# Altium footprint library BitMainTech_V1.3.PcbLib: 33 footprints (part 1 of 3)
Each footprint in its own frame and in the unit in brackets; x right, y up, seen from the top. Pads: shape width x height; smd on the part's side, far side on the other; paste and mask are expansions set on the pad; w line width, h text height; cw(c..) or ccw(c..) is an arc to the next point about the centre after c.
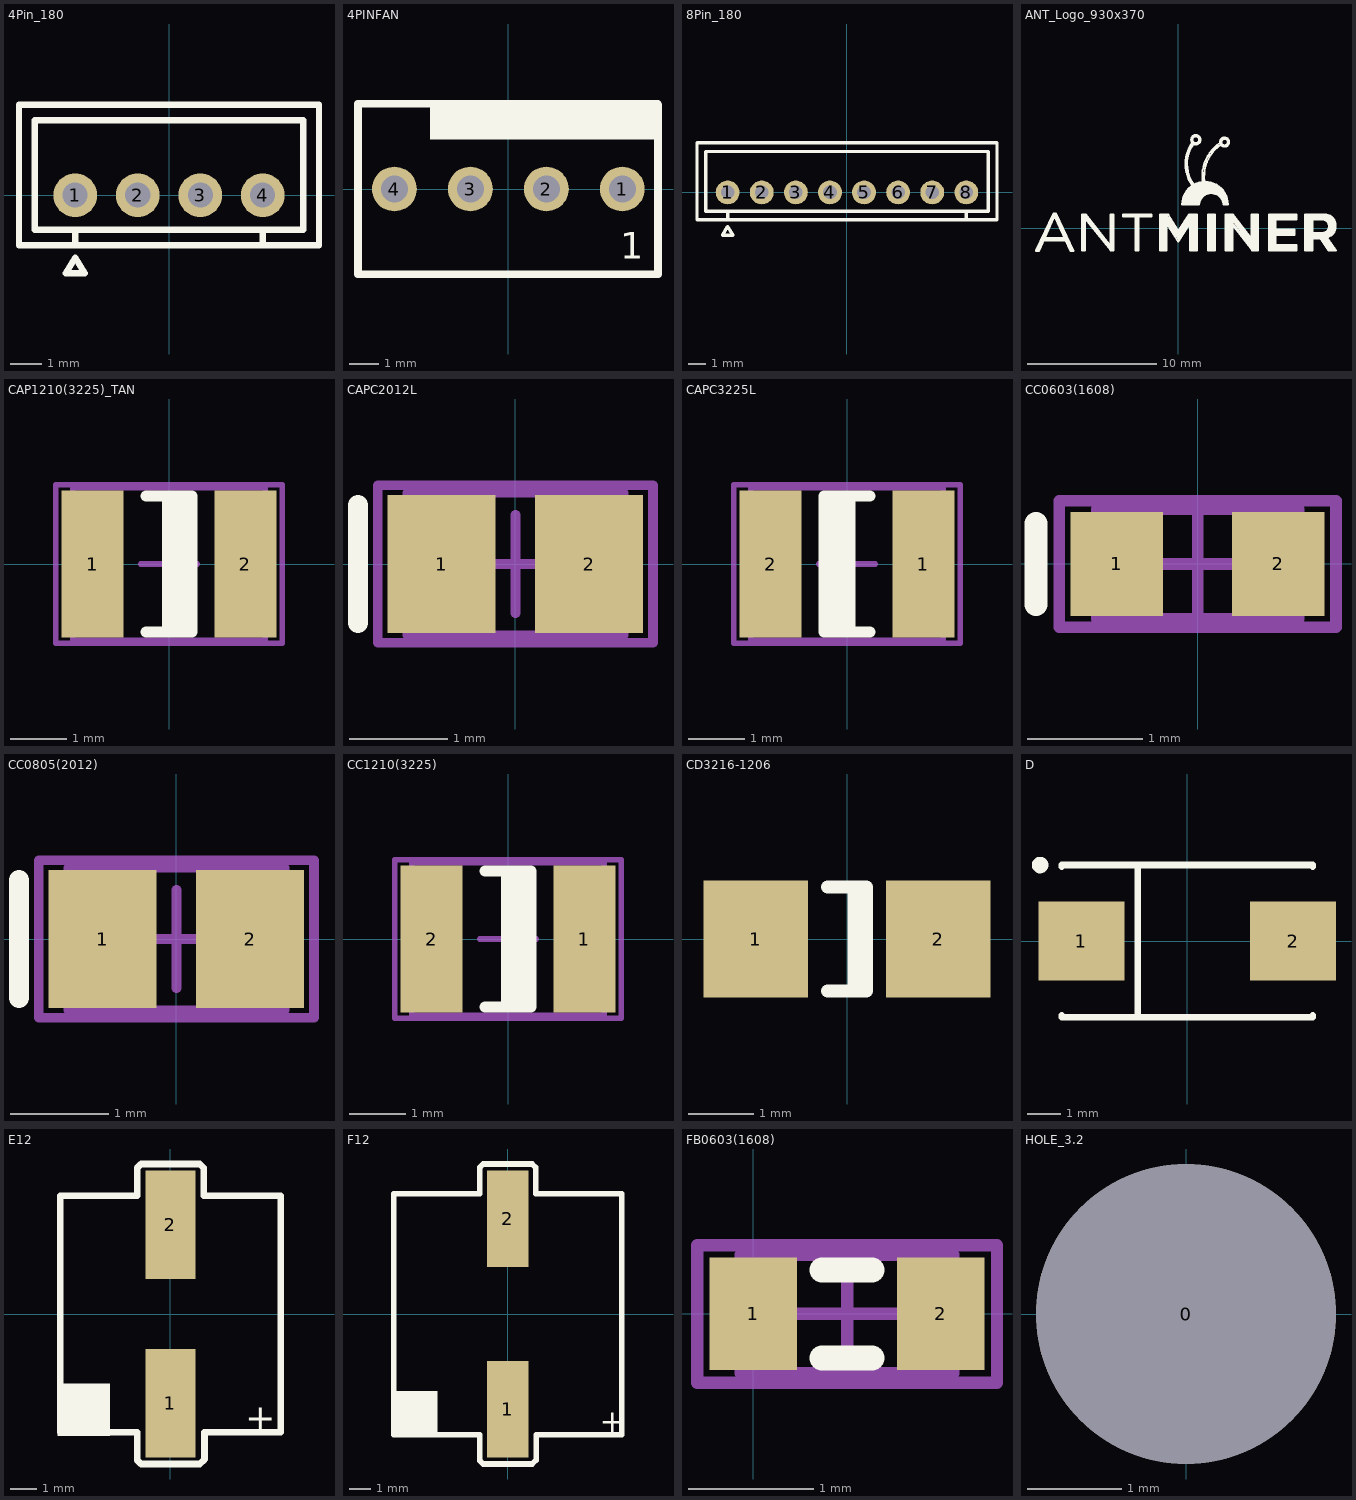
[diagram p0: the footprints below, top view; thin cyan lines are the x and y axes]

## 4Pin_180 [mm]
height 6.8
pads (4):
  round 1.4 hole 0.8: 1(-3,0) 2(-1,0) 3(1,0) 4(3,0)
Top Overlay:
  lines w0.203: -3,-1.6 -3,-1.1 ; 3,-1.6 3,-1.1 ; -4.8,-1.6 4.8,-1.6 4.8,2.9 -4.8,2.9 -4.8,-1.6 ; -4.3,-1.1 4.3,-1.1 4.3,2.4 -4.3,2.4 -4.3,-1.1 ; -3.3,-2.5 -3,-2 -2.7,-2.5 -3.3,-2.5

## 4PINFAN [mm]
height 18.15
pads (4):
  round 1.5 hole 0.9 paste+0.05 mask+0.05: 1(3.81,0) 2(1.27,0) 3(-1.27,0) 4(-3.81,0)
Top Overlay:
  rectangle: -2.617,1.651 4.927,2.794
  lines w0.254: 5,2.85 -5.029,2.85 -5.029,-2.845 -5.024,-2.85 5.004,-2.85 5.004,2.819
  text "1" at 3.734,-2.337 h0.89

## 8Pin_180 [mm]
height 6.8
pads (8):
  round 1.4 hole 0.8: 1(-7,0) 2(-5,0) 3(-3,0) 4(-1,0) 5(1,0) 6(3,0) 7(5,0) 8(7,0)
Top Overlay:
  lines w0.203: -7,-1.6 -7,-1.1 ; 7,-1.6 7,-1.1 ; -8.8,-1.6 -8.8,2.9 8.8,2.9 8.8,-1.6 -8.8,-1.6 ; -8.3,-1.1 -8.3,2.4 8.3,2.4 8.3,-1.1 -8.3,-1.1 ; -7.3,-2.5 -6.7,-2.5 -7,-2 -7.3,-2.5

## ANT_Logo_930x370 [mm]
height 18.15
Top Overlay:
  drawing of 187 lines, arcs and shapes, not listed

## CAP1210(3225)_TAN [mm] "Chip Capacitor, Body 3.2x2.5mm, IPC High Density"
height 1.35
pads (2):
  rect 1.1x2.6 smd: 1(-1.35,0) 2(1.35,0)
Top Overlay:
  rectangle: -0.125,-1.2 0.425,1.2
  lines w0.2: -0.4,-1.2 0.4,-1.2 0.4,1.2 -0.4,1.2
Mechanical 13:
  lines w0.1: -1.7,-1.35 1.7,-1.35 1.7,1.35 -1.7,1.35 -1.7,-1.35
Mechanical 15:
  lines w0.1: -0.5,0 0.5,0 ; 0,-0.5 0,0.5 ; -2,-1.4 2,-1.4 2,1.4 -2,1.4 -2,-1.4
3D body: height 1.35, standoff 0, extent -1.7,-1.35 1.7,1.35

## CAPC2012L [mm] "Chip Capacitor, Body 2.0x1.3mm, IPC High Density"
height 1.1
pads (2):
  rect 1.1x1.4 smd: 1(-0.75,0) 2(0.75,0)
Top Overlay:
  lines w0.2: -1.6,-0.6 -1.6,0.6
Mechanical 13:
  lines w0.1: -1.1,-0.725 1.1,-0.725 1.1,0.725 -1.1,0.725 -1.1,-0.725
Mechanical 15:
  lines w0.1: -0.5,0 0.5,0 ; 0,-0.5 0,0.5 ; -1.4,-0.8 1.4,-0.8 1.4,0.8 -1.4,0.8 -1.4,-0.8
3D body: height 1.1, standoff 0, extent -1.1,-0.725 1.1,0.725

## CAPC3225L [mm] "Chip Capacitor, Body 3.2x2.5mm, IPC High Density"
height 1.35
pads (2):
  rect 1.1x2.6 smd: 1(1.35,0) 2(-1.35,0)
Top Overlay:
  rectangle: -0.4,-1.2 0.15,1.2
  lines w0.2: 0.4,-1.2 -0.4,-1.2 -0.4,1.2 0.4,1.2
Mechanical 13:
  lines w0.1: -1.7,-1.35 -1.7,1.35 1.7,1.35 1.7,-1.35 -1.7,-1.35
Mechanical 15:
  lines w0.1: -0.5,0 0.5,0 ; 0,-0.5 0,0.5 ; -2,-1.4 -2,1.4 2,1.4 2,-1.4 -2,-1.4
3D body: height 1.35, standoff 0, extent -1.7,-1.35 1.7,1.35

## CC0603(1608) [mm] "Chip Capacitor, Body 1.6x0.8mm, IPC High Density"
height 0.85
pads (2):
  rect 0.8x0.9 smd: 1(-0.7,0) 2(0.7,0)
Top Overlay:
  lines w0.2: -1.4,-0.35 -1.4,0.35
Mechanical 13:
  lines w0.1: -0.875,-0.475 0.875,-0.475 0.875,0.475 -0.875,0.475 -0.875,-0.475
Mechanical 15:
  lines w0.1: -0.475,0 0.475,0 ; 0,-0.475 0,0.475 ; -1.2,-0.55 1.2,-0.55 1.2,0.55 -1.2,0.55 -1.2,-0.55
3D body: height 0.85, standoff 0, extent -0.875,-0.475 0.875,0.475

## CC0805(2012) [mm] "Chip Capacitor, Body 2.0x1.3mm, IPC High Density"
height 1.1
pads (2):
  rect 1.1x1.4 smd: 1(-0.75,0) 2(0.75,0)
Top Overlay:
  lines w0.2: -1.6,-0.6 -1.6,0.6
Mechanical 13:
  lines w0.1: -1.1,-0.725 -1.1,0.725 1.1,0.725 1.1,-0.725 -1.1,-0.725
Mechanical 15:
  lines w0.1: -0.5,0 0.5,0 ; 0,-0.5 0,0.5 ; -1.4,-0.8 -1.4,0.8 1.4,0.8 1.4,-0.8 -1.4,-0.8
3D body: height 1.1, standoff 0, extent -1.1,-0.725 1.1,0.725

## CC1210(3225) [mm] "Chip Capacitor, Body 3.2x2.5mm, IPC High Density"
height 1.35
pads (2):
  rect 1.1x2.6 smd: 1(1.35,0) 2(-1.35,0)
Top Overlay:
  rectangle: -0.125,-1.2 0.425,1.2
  lines w0.2: -0.4,-1.2 0.4,-1.2 0.4,1.2 -0.4,1.2
Mechanical 13:
  lines w0.1: -1.7,-1.35 1.7,-1.35 1.7,1.35 -1.7,1.35 -1.7,-1.35
Mechanical 15:
  lines w0.1: -0.5,0 0.5,0 ; 0,-0.5 0,0.5 ; -2,-1.4 2,-1.4 2,1.4 -2,1.4 -2,-1.4
3D body: height 1.35, standoff 0, extent -1.7,-1.35 1.7,1.35

## CD3216-1206 [mm] "Chip Diode; Body 3.2 x 1.6 mm (LxW typ)"
height 1.35
pads (2):
  rect 1.6x1.8 smd: 1(-1.4,0) 2(1.4,0)
Top Overlay:
  lines w0.2: -0.3,-0.8 0.3,-0.8 0.3,0.8 -0.3,0.8 ; 0.11,-0.8 0.11,0.8

## D [mm] "Capacitor, SM Tantalum; Body 7.3 x 4.3 mm (LxW typ)"
height 3.1
pads (2):
  rect 2.6x2.4 smd: 1(-3.2,0) 2(3.2,0)
Top Overlay:
  circle w0.25: c-4.45,2.3 r0.125
  lines w0.2: -3.8,-2.25 -3.8,-2.3 3.8,-2.3 3.8,-2.25 ; -3.8,2.25 -3.8,2.3 3.8,2.3 3.8,2.25 ; -1.5,-2.3 -1.5,2.3

## E12 [mm] "SVP"
height 8.3
pads (2):
  rect 1.9x4.15 smd: 1(0,-3.4) 2(0,3.4)
Top Overlay:
  rectangle: -4.311,-4.641 -2.311,-2.641
  lines w0.254: -4.2,-4.5 -4.2,4.5 -2.333,4.5 -1.27,4.5 -1.27,5.563 -1.118,5.715 1.118,5.715 1.27,5.563 1.27,4.5 2.333,4.5 4.2,4.5 4.2,-4.5 2.333,-4.5 1.295,-4.5 1.295,-5.537 1.118,-5.715 -1.118,-5.715 -1.27,-5.563 -1.27,-4.5 -2.333,-4.5 -4.2,-4.5
  text "+" at 2.845,-4.445 h1.02
3D body: height 0.8, standoff 0, extent -3.984,-3.992 3.984,3.992
3D body: height 12.8, standoff 0.8, extent -3.968,-3.992 4,3.992

## F12 [mm] "SVP"
height 10.3
pads (2):
  rect 1.9x4.4 smd: 1(0,-4.35) 2(0,4.35)
Top Overlay:
  region: -5.2,-3.5 -5.2,-5.5 -3.2,-5.5 -3.2,-3.5
  lines w0.254: -5.2,-5.5 -1.27,-5.5 -1.27,-6.69 -1.12,-6.84 1.115,-6.84 1.295,-6.66 1.295,-5.5 5.2,-5.5 5.2,5.5 1.27,5.5 1.27,6.695 1.115,6.85 -1.12,6.85 -1.27,6.7 -1.27,5.5 -5.2,5.5 -5.2,-5.5
  text "+" at 4.21,-5.39 h1.02
3D body: height 13.4, standoff 0.8, extent -4.96,-4.99 5,4.99
3D body: height 0.8, standoff 0, extent -5,-5.29 5.01,5.28

## FB0603(1608) [mm] "Ferrite Bead"
pads (2):
  rect 0.7x0.9 smd: 1(0,0) 2(1.5,0)
Top Overlay:
  lines w0.2: 0.55,-0.35 0.95,-0.35 ; 0.55,0.35 0.95,0.35
Mechanical 13:
  lines w0.1: -0.1,-0.475 -0.1,0.475 1.6,0.475 1.6,-0.475 -0.1,-0.475
Mechanical 15:
  lines w0.1: 0.275,0 1.225,0 ; 0.75,-0.475 0.75,0.475 ; -0.45,-0.55 -0.45,0.55 1.95,0.55 1.95,-0.55 -0.45,-0.55
3D body: height 0.6, standoff 0, extent -0.1,-0.475 1.6,0.475

## HOLE_3.2 [mm]
pads (1):
  round 3.2 hole 3.2 unplated: 0(0,0)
